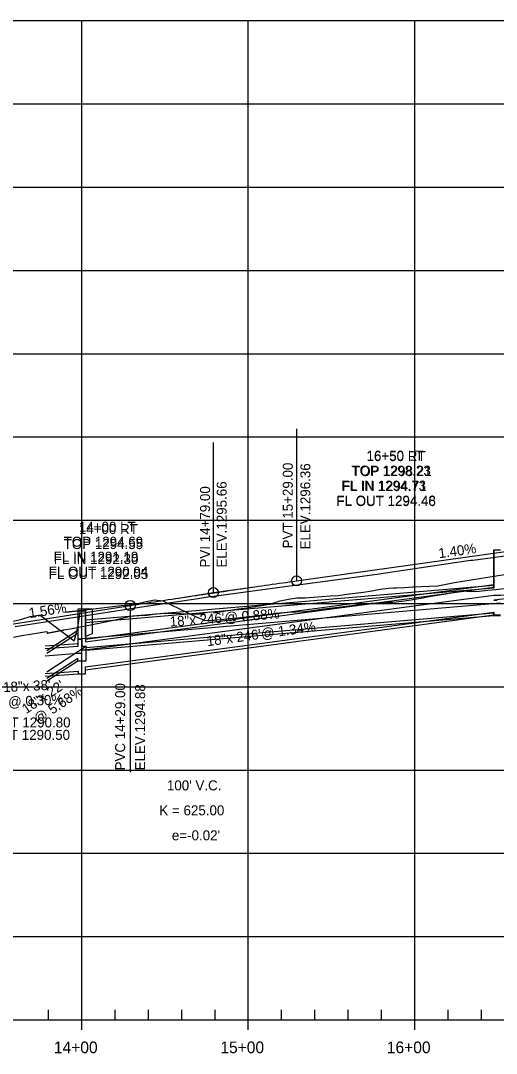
# Model space of a CAD drawing. Extents: x 670877 to 686811, y 705985 to 708501.
# Drawn here: x 684841 to 685126, y 707873 to 708493 of the extents above; entities that cross this region are included whole.
import ezdxf

# ---------------------------------------------------------------- set-up
doc = ezdxf.new("R2010")
doc.units = 0
for name, color, linetype in [('30', 7, 'Continuous'), ('37', 7, 'Continuous'), ('DRAINAGE_HGL LEFT', 7, 'Continuous'), ('DRAINAGE_HGL RIGHT', 7, 'Continuous'), ('Profile Drainage Annot Left', 7, 'Continuous'), ('Profile Drainage Annot Right', 7, 'Continuous'), ('R_Drainage Extensions_LEFT', 7, 'Continuous'), ('R_Drainage LEFT', 7, 'Continuous'), ('R_Drainage RIGHT', 7, 'Continuous'), ('R_Exist Surface', 7, 'Continuous'), ('R_Profile Work Left', 7, 'Continuous'), ('R_Profile Work Right', 7, 'Continuous'), ('R_Vert Alg', 7, 'Continuous'), ('R_Vert Alg Annot', 7, 'Continuous')]:
    doc.layers.add(name, color=color, linetype=linetype)

msp = doc.modelspace()

# ---------------------------------------------------------------- linework, layer by layer
at = {"layer": '37'}
for p, q in [((684477.28, 708492.85), (686777.28, 708492.85)), ((684877.28, 707892.85), (684877.28, 708492.85)), ((684977.28, 707892.85), (684977.28, 708492.85)), ((685077.28, 707892.85), (685077.28, 708492.85)), ((684477.28, 708442.85), (686777.28, 708442.85)), ((684477.28, 708392.85), (686777.28, 708392.85)), ((684477.28, 708342.85), (686777.28, 708342.85)), ((684477.28, 708292.85), (686777.28, 708292.85)), ((684477.28, 708242.85), (686777.28, 708242.85)), ((684477.28, 708192.85), (686777.28, 708192.85)), ((684477.28, 708142.85), (686777.28, 708142.85)), ((684477.28, 708092.85), (686777.28, 708092.85)), ((684477.28, 708042.85), (686777.28, 708042.85)), ((684477.28, 707992.85), (686777.28, 707992.85)), ((684477.28, 707942.85), (686777.28, 707942.85)), ((684857.28, 707892.85), (684857.28, 707898.85)), ((684897.28, 707892.85), (684897.28, 707898.85)), ((684917.28, 707892.85), (684917.28, 707898.85)), ((684937.28, 707892.85), (684937.28, 707898.85)), ((684957.28, 707892.85), (684957.28, 707898.85)), ((684997.28, 707892.85), (684997.28, 707898.85)), ((685017.28, 707892.85), (685017.28, 707898.85)), ((685037.28, 707892.85), (685037.28, 707898.85)), ((685057.28, 707892.85), (685057.28, 707898.85)), ((685097.28, 707892.85), (685097.28, 707898.85)), ((685117.28, 707892.85), (685117.28, 707898.85)), ((684477.28, 707892.85), (686777.28, 707892.85)), ((684877.28, 707886.85), (684877.28, 707892.85)), ((684977.28, 707886.85), (684977.28, 707892.85)), ((685077.28, 707886.85), (685077.28, 707892.85))]:
    msp.add_line(p, q, dxfattribs=at)
at = {"layer": 'DRAINAGE_HGL LEFT'}
msp.add_lwpolyline([(684855.2, 708111.48), (684875.01, 708112.97), (684877.28, 708112.97), (684877.28, 708115), (684879.28, 708115), (685124.73, 708147.9), (685126.73, 708147.9), (685126.73, 708147.9), (685128.73, 708147.9), (685230.25, 708157.07), (685232.25, 708157.07), (685232.25, 708158.42), (685234.25, 708158.42), (685525.17, 708185.62), (685527.18, 708185.62), (685527.18, 708186.58), (685529.23, 708186.58), (685617.8, 708197.78), (685619.52, 708197.78)], dxfattribs=at)
at = {"layer": 'DRAINAGE_HGL RIGHT'}
for points in [[(685234.25, 708157.7), (685124.73, 708144.8), (685126.73, 708144.8)], [(685128.73, 708143.15), (684875.28, 708121.55), (684877.28, 708121.55), (684877.28, 708117.21), (684880.1, 708117.21), (684856.31, 708101.71)]]:
    msp.add_lwpolyline(points, dxfattribs=at)
at = {"layer": 'R_Drainage Extensions_LEFT'}
msp.add_lwpolyline([(684879.41, 708139.75), (684883.41, 708139.75), (684883.41, 708124.75), (684879.41, 708123.08), (684879.41, 708139.75)], dxfattribs=at)
at = {"layer": 'R_Drainage LEFT'}
for points in [[(685124.73, 708152.65), (685124.73, 708175.11)], [(685124.73, 708175.11), (685128.73, 708175.11)], [(684879.41, 708121.43), (685124.73, 708154.31)], [(684879.41, 708119.77), (685124.73, 708152.65)], [(684875.15, 708117.26), (684875.15, 708139.75)], [(684875.15, 708139.75), (684879.41, 708139.75)], [(684879.41, 708139.75), (684879.41, 708119.77)], [(684879.41, 708104.77), (685124.73, 708137.65)], [(684879.41, 708103.1), (685124.73, 708135.98)], [(685124.73, 708137.65), (685124.73, 708135.98)], [(685124.73, 708135.98), (685128.73, 708135.98)], [(684855.2, 708117.5), (684875.15, 708118.92)], [(684855.2, 708115.83), (684875.15, 708117.26)], [(684879.41, 708100.59), (684879.41, 708104.77)], [(684855.2, 708100.83), (684875.15, 708102.26)], [(684855.2, 708099.16), (684875.15, 708100.59)], [(684875.15, 708102.26), (684875.15, 708100.59)], [(684875.15, 708100.59), (684879.41, 708100.59)]]:
    msp.add_lwpolyline(points, dxfattribs=at)
at = {"layer": 'R_Drainage RIGHT'}
for points in [[(685128.73, 708174.95), (685124.73, 708174.95)], [(685124.73, 708174.95), (685124.73, 708152.11)], [(685124.73, 708153.77), (684879.69, 708132.89)], [(685124.73, 708152.11), (684879.69, 708131.22)], [(684879.69, 708138.35), (684874.87, 708138.35)], [(684874.87, 708138.35), (684874.87, 708124.94)], [(684879.69, 708131.22), (684879.69, 708138.35)], [(685124.73, 708137.11), (684879.69, 708116.22)], [(685124.73, 708135.44), (684879.69, 708114.56)], [(685124.73, 708135.44), (685124.73, 708137.11)], [(685128.73, 708135.44), (685124.73, 708135.44)], [(684874.87, 708126.61), (684856.31, 708114.51)], [(684874.87, 708124.94), (684856.31, 708112.85)], [(684879.69, 708116.22), (684879.69, 708108.27)], [(684874.87, 708109.94), (684856.31, 708097.85)], [(684874.87, 708108.27), (684856.31, 708096.18)], [(684874.87, 708108.27), (684874.87, 708109.94)], [(684879.69, 708108.27), (684874.87, 708108.27)]]:
    msp.add_lwpolyline(points, dxfattribs=at)
at = {"layer": 'R_Exist Surface'}
msp.add_lwpolyline([(684837.23, 708129.11), (684911.97, 708140.71), (684918.62, 708141.73), (684918.68, 708141.74), (684918.76, 708141.74), (684947.01, 708145.9), (684953.03, 708146.78), (684953.05, 708146.79), (684956.5, 708147.26), (685003.66, 708153.62), (685004, 708153.67), (685056.07, 708160.64), (685057.13, 708160.82), (685110.78, 708168.79), (685112.1, 708168.96), (685162.81, 708175.65)], dxfattribs=at)
at = {"layer": 'R_Profile Work Left'}
for points in [[(684951.03, 708132.56), (684956.03, 708132.82), (684961.03, 708133.18), (684966.03, 708133.76), (684971.03, 708134.35), (684976.02, 708134.93), (684981.02, 708135.51), (684986.02, 708136.1), (684991.02, 708136.68), (684996.02, 708137.19), (685001.02, 708137.65), (685006.02, 708137.94), (685011.02, 708138.16), (685016.02, 708138.75), (685021.02, 708139.39), (685026.02, 708140.03), (685031.02, 708140.68), (685036.02, 708141.32), (685041.02, 708141.96), (685046.02, 708142.6), (685051.01, 708143.08), (685056.01, 708143.39), (685061.01, 708143.64), (685064.01, 708143.75), (685066.01, 708143.82), (685071.01, 708144.41), (685076.01, 708145.27), (685077.01, 708145.44), (685081.01, 708146.14), (685086.01, 708147), (685091.01, 708147.86), (685096.01, 708148.73), (685101.01, 708149.59), (685106.01, 708150.46), (685111.01, 708150.11), (685116.01, 708150.28), (685121.01, 708150.79), (685126, 708151.29), (685131, 708151.92)], [(684836.28, 708132.34), (684841.28, 708133.38), (684846.28, 708135), (684851.28, 708135.78), (684852.28, 708135.91), (684872.66, 708120.39), (684873.06, 708121.65), (684873.47, 708123.06), (684873.88, 708124.63), (684874.29, 708126.41), (684874.77, 708128.59), (684875.25, 708131.06), (684875.73, 708133.85), (684876.21, 708137), (684876.11, 708138.29), (684875.63, 708138.27), (684875.1, 708138.25), (684874.53, 708138.22), (684873.91, 708138.18), (684873.26, 708138.13), (684872.57, 708138.07), (684871.85, 708138.01), (684871.65, 708137.99), (684871.11, 708137.94), (684870.35, 708137.86), (684869.56, 708137.78), (684868.77, 708137.69), (684867.97, 708137.6), (684867.73, 708137.57), (684870.94, 708137.97), (684875.94, 708138.6), (684876.94, 708138.72), (684880.94, 708139.22), (684885.94, 708139.85), (684886.17, 708139.88), (684890.94, 708140.47), (684895.94, 708141.03), (684900.94, 708141.59), (684905.95, 708142.14), (684910.95, 708142.77), (684915.94, 708144.05), (684920.94, 708145.05), (684925.95, 708144.51), (684930.97, 708142.1), (684935.98, 708139.69), (684941, 708137.29), (684946.01, 708134.88), (684951.03, 708132.79)]]:
    msp.add_lwpolyline(points, dxfattribs=at)
at = {"layer": 'R_Profile Work Right'}
for points in [[(684956.44, 708137.34), (684961.44, 708138.08), (684966.44, 708138.83), (684971.44, 708139.57), (684976.44, 708140.31), (684981.44, 708141.05), (684986.44, 708141.94), (684991.44, 708142.82), (684996.44, 708144.42), (685001.44, 708145.53), (685006.44, 708146.2), (685011.44, 708146.19), (685016.44, 708146.71), (685021.44, 708147.06), (685026.44, 708147.41), (685031.44, 708147.76), (685036.44, 708148.56), (685041.44, 708149.13), (685046.45, 708149.61), (685051.44, 708150.52), (685056.44, 708151.43), (685061.44, 708152.12), (685064.44, 708152.27), (685066.08, 708152.34), (685071.08, 708152.56), (685076.08, 708152.78), (685077.08, 708152.82), (685081.07, 708153), (685086.07, 708153.22), (685091.07, 708153.47), (685096.07, 708154.44), (685101.07, 708155.4), (685106.07, 708156.28), (685111.07, 708157.09), (685116.08, 708157.9), (685121.08, 708158.71), (685126.08, 708159.52), (685131.08, 708160.33)], [(684836.28, 708122.59), (684841.28, 708123.59), (684846.28, 708124.41), (684851.28, 708125.24), (684852.28, 708125.4), (684856.28, 708126.07), (684856.52, 708125.08), (684856.59, 708125.09), (684856.69, 708125.11), (684856.83, 708125.14), (684857.02, 708125.17), (684857.24, 708125.21), (684857.5, 708125.26), (684857.8, 708125.32), (684858.14, 708125.38), (684858.51, 708125.46), (684858.91, 708125.53), (684859.34, 708125.62), (684859.81, 708125.7), (684860.3, 708125.8), (684860.81, 708125.9), (684861.35, 708126), (684861.5, 708126.03), (684861.91, 708126.11), (684862.48, 708126.22), (684863.07, 708126.33), (684863.68, 708126.44), (684864.29, 708126.56), (684864.92, 708126.68), (684865.54, 708126.8), (684866.17, 708126.92), (684866.5, 708126.98), (684871.5, 708127.94), (684876.49, 708128.9), (684877.49, 708129.09), (684881.49, 708129.85), (684886.49, 708130.81), (684886.72, 708130.85), (684891.49, 708131.77), (684896.49, 708132.8), (684901.49, 708134.02), (684906.49, 708135.2), (684911.48, 708135.69), (684916.48, 708135.91), (684921.48, 708136.68), (684926.47, 708137.08), (684931.47, 708137.06), (684936.46, 708136.9), (684941.45, 708136.73), (684946.45, 708136.57), (684951.44, 708136.59)]]:
    msp.add_lwpolyline(points, dxfattribs=at)
at = {"layer": 'R_Vert Alg'}
for p, q in [((685006.28, 708156.45), (685226.28, 708187.25)), ((684931.28, 708145.55), (684956.28, 708149.45)), ((684956.28, 708149.45), (684981.28, 708152.95)), ((684831.28, 708129.95), (684906.28, 708141.65))]:
    msp.add_line(p, q, dxfattribs=at)
msp.add_lwpolyline([(684906.28, 708141.65), (684908.36, 708141.97), (684910.44, 708142.3), (684912.53, 708142.62), (684914.61, 708142.94), (684916.69, 708143.26), (684918.78, 708143.59), (684920.86, 708143.91), (684922.94, 708144.23), (684925.03, 708144.54), (684927.11, 708144.86), (684929.19, 708145.18), (684931.28, 708145.5), (684933.36, 708145.81), (684935.44, 708146.13), (684937.53, 708146.44), (684939.61, 708146.76), (684941.69, 708147.07), (684943.78, 708147.39), (684945.86, 708147.7), (684947.94, 708148.01), (684950.03, 708148.32), (684952.11, 708148.63), (684954.19, 708148.94), (684958.36, 708149.56), (684960.44, 708149.86), (684962.53, 708150.17), (684964.61, 708150.48), (684966.69, 708150.78), (684968.78, 708151.09), (684970.86, 708151.39), (684972.94, 708151.69), (684975.03, 708151.99), (684977.11, 708152.3), (684979.19, 708152.6), (684981.28, 708152.9), (684983.36, 708153.2), (684985.44, 708153.5), (684987.53, 708153.79), (684989.61, 708154.09), (684991.69, 708154.39), (684993.78, 708154.69), (684995.86, 708154.98), (684997.94, 708155.28), (685000.03, 708155.57), (685002.11, 708155.86), (685004.19, 708156.16), (685006.28, 708156.45)], dxfattribs=at)
for centre in [(685006.28, 708156.45), (684956.28, 708149.45), (684906.28, 708141.65)]:
    msp.add_circle(centre, 3, dxfattribs=at)
at = {"layer": 'R_Vert Alg Annot'}
for p, q in [((685006.28, 708247.8), (685006.28, 708156.45)), ((684956.28, 708149.45), (684956.28, 708239.45)), ((684906.28, 708141.65), (684906.28, 708041.65))]:
    msp.add_line(p, q, dxfattribs=at)

# ---------------------------------------------------------------- texts
at = {"layer": '30'}
for s, p in [('14+00', (684860.47, 707872.85)), ('15+00', (684960.47, 707872.85)), ('16+00', (685060.47, 707872.85))]:
    msp.add_text(s, height=7, dxfattribs=at).set_placement(p)
at = {"layer": 'Profile Drainage Annot Left'}
for s, p in [('16+50 LT', (685048.29, 708228.66)), ('TOP 1298.23', (685039.18, 708219.66)), ('FL IN 1294.73', (685033.18, 708210.66)), ('FL OUT 1294.48', (685030.19, 708201.66)), ('14+00 LT', (684875.48, 708185.96)), ('TOP 1294.69', (684866.34, 708176.96)), ('FL IN 1291.19', (684860.34, 708167.96)), ('FL OUT 1290.94', (684857.37, 708158.96)), ('FL OUT 1290.80', (684810.74, 708068.45))]:
    msp.add_text(s, height=6, dxfattribs=at).set_placement(p)
for s, rotation, p in [('18"x 246\'@ 1.34%', 7.85515, (684952.67, 708117.18)), ('18"x 38\'', 2.8769, (684830.15, 708089.62)), ('@ 0.30%', 2.8769, (684833.15, 708080.76))]:
    msp.add_text(s, height=6, rotation=rotation, dxfattribs=at).set_placement(p)
at = {"layer": 'Profile Drainage Annot Right'}
for s, p in [('16+50 RT', (685048.29, 708228.36)), ('TOP 1298.21', (685039.61, 708219.36)), ('FL IN 1294.71', (685033.61, 708210.36)), ('FL OUT 1294.46', (685030.18, 708201.36)), ('14+00 RT', (684875.48, 708184.56)), ('TOP 1294.55', (684866.37, 708175.56)), ('FL IN 1292.30', (684860.41, 708166.56)), ('FL OUT 1292.05', (684857.37, 708157.56)), ('FL OUT 1290.50', (684810.42, 708061))]:
    msp.add_text(s, height=6, dxfattribs=at).set_placement(p)
for s, rotation, p in [('18"x 246\'@ 0.88%', 4.345, (684930.3, 708128.92)), ('18"x 22\'', 33.84805, (684843.81, 708076.34)), ('@ 5.68%', 33.84805, (684850.94, 708070.28))]:
    msp.add_text(s, height=6, rotation=rotation, dxfattribs=at).set_placement(p)
at = {"layer": 'R_Vert Alg Annot'}
for s, rotation, p in [('PVT 15+29.00', 90, (685003.98, 708175.93)), ('ELEV.1296.36', 90, (685014.54, 708175.31)), ('ELEV.1295.66', 90, (684964.28, 708164.45)), ('PVI 14+79.00', 90, (684954.28, 708164.45)), ('1.40%', 7.96961, (685091.94, 708170.01)), ('1.56%', 8.86668, (684845.9, 708134.07)), ('PVC 14+29.00', 90, (684903.28, 708042.65)), ('ELEV.1294.88', 90, (684915.28, 708042.65))]:
    msp.add_text(s, height=6, rotation=rotation, dxfattribs=at).set_placement(p)
for s, p in [("100' V.C.", (684928.36, 708030.66)), ('K = 625.00', (684923.85, 708015.66)), ("e=-0.02'", (684931.36, 708000.66))]:
    msp.add_text(s, height=6, dxfattribs=at).set_placement(p)

doc.saveas('drawing.dxf')
